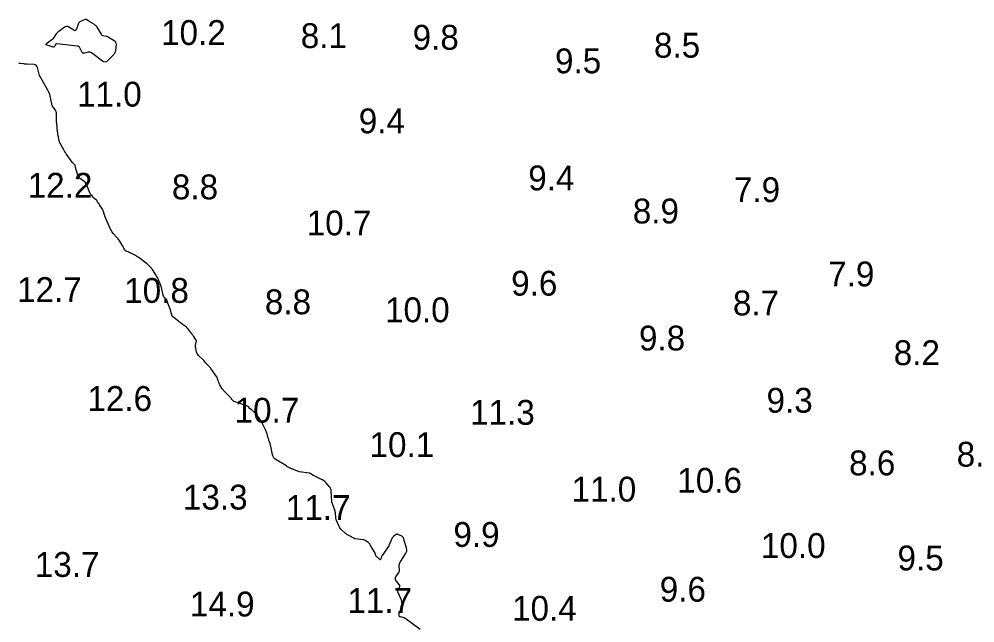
# Model space of a CAD drawing. Extents: x 815352 to 820877, y 582403 to 597439.
# Drawn here: x 819249.1 to 819441.4, y 594050.8 to 594172.3 of the extents above; entities that cross this region are included whole.
import ezdxf

# ---------------------------------------------------------------- set-up
doc = ezdxf.new("R2010")
doc.units = 0
doc.layers.add('V-CONT-EL12', color=7, linetype='Continuous')
doc.layers.add('V-TOPO-SOUN', color=7, linetype='Continuous')

msp = doc.modelspace()

# ---------------------------------------------------------------- linework, layer by layer
at = {"layer": 'V-CONT-EL12'}
msp.add_lwpolyline([(819256.61, 594167.35), (819256.52, 594167.32), (819256.45, 594167.27), (819256.4, 594167.18), (819256.22, 594166.79), (819256.16, 594166.71), (819256.1, 594166.66), (819256.01, 594166.65), (819255.92, 594166.66), (819254.73, 594167.04), (819254.55, 594167.12), (819254.47, 594167.22), (819254.51, 594167.34), (819254.65, 594167.48), (819255.91, 594168.42), (819255.92, 594168.43), (819255.93, 594168.43), (819255.94, 594168.43), (819255.95, 594168.43), (819255.99, 594168.41), (819256, 594168.41), (819256.01, 594168.41), (819256.01, 594168.41), (819256.02, 594168.42), (819256.61, 594169.33), (819256.71, 594169.48), (819256.83, 594169.62), (819256.96, 594169.75), (819257.1, 594169.88), (819258.15, 594170.72), (819258.37, 594170.85), (819258.6, 594170.91), (819258.84, 594170.88), (819259.08, 594170.77), (819260.11, 594170.13), (819260.3, 594170.04), (819260.46, 594170.05), (819260.59, 594170.14), (819260.69, 594170.34), (819261.03, 594171.39), (819261.1, 594171.56), (819261.21, 594171.7), (819261.35, 594171.82), (819261.52, 594171.91), (819262.46, 594172.29), (819262.54, 594172.31), (819262.61, 594172.31), (819262.67, 594172.29), (819262.74, 594172.24), (819262.99, 594172.03), (819263.05, 594171.98), (819263.12, 594171.93), (819263.19, 594171.88), (819263.26, 594171.84), (819264.18, 594171.28), (819264.35, 594171.16), (819264.5, 594171.02), (819264.63, 594170.87), (819264.75, 594170.7), (819265.57, 594169.28), (819265.65, 594169.16), (819265.75, 594169.08), (819265.87, 594169.02), (819266, 594168.98), (819266.57, 594168.9), (819266.71, 594168.87), (819266.85, 594168.83), (819266.98, 594168.77), (819267.1, 594168.7), (819268.19, 594168.01), (819268.38, 594167.85), (819268.51, 594167.66), (819268.57, 594167.45), (819268.58, 594167.2), (819268.47, 594166.02), (819268.42, 594165.74), (819268.33, 594165.49), (819268.19, 594165.25), (819268.01, 594165.04), (819266.9, 594163.91), (819266.65, 594163.71), (819266.38, 594163.64), (819266.11, 594163.68), (819265.83, 594163.84), (819263.65, 594165.5), (819263.49, 594165.6), (819263.33, 594165.66), (819263.15, 594165.67), (819262.97, 594165.65), (819262.21, 594165.46), (819262.04, 594165.44), (819261.89, 594165.47), (819261.77, 594165.57), (819261.68, 594165.71), (819261.23, 594166.69), (819261.21, 594166.72), (819261.19, 594166.74), (819261.16, 594166.76), (819261.13, 594166.78), (819260.99, 594166.83), (819260.96, 594166.84), (819260.92, 594166.85), (819260.89, 594166.86), (819260.85, 594166.86), (819256.7, 594167.35)], close=True, dxfattribs=at)
msp.add_lwpolyline([(819329.79, 594049.45), (819326.67, 594051.71), (819326.57, 594051.78), (819326.47, 594051.83), (819326.36, 594051.87), (819326.25, 594051.9), (819325.78, 594051.99), (819325.68, 594052.02), (819325.61, 594052.08), (819325.56, 594052.16), (819325.54, 594052.27), (819325.51, 594052.97), (819325.51, 594053.01), (819325.52, 594053.04), (819325.55, 594053.06), (819325.59, 594053.08), (819325.75, 594053.11), (819325.79, 594053.13), (819325.82, 594053.15), (819325.84, 594053.18), (819325.85, 594053.21), (819326.09, 594054.47), (819326.12, 594054.7), (819326.11, 594054.91), (819326.07, 594055.13), (819325.99, 594055.34), (819325.33, 594056.91), (819325.28, 594057.05), (819325.27, 594057.18), (819325.29, 594057.32), (819325.35, 594057.45), (819325.63, 594057.98), (819325.67, 594058.11), (819325.68, 594058.24), (819325.65, 594058.36), (819325.58, 594058.48), (819324.89, 594059.34), (819324.78, 594059.51), (819324.75, 594059.69), (819324.77, 594059.88), (819324.87, 594060.06), (819325.49, 594060.93), (819325.56, 594061.05), (819325.6, 594061.18), (819325.62, 594061.31), (819325.61, 594061.45), (819325.53, 594062.09), (819325.52, 594062.19), (819325.53, 594062.29), (819325.54, 594062.39), (819325.57, 594062.49), (819325.69, 594062.87), (819325.72, 594062.97), (819325.76, 594063.06), (819325.81, 594063.15), (819325.86, 594063.23), (819326.83, 594064.67), (819326.98, 594064.94), (819327.06, 594065.22), (819327.07, 594065.52), (819327.02, 594065.82), (819326.5, 594067.65), (819326.47, 594067.74), (819326.43, 594067.82), (819326.38, 594067.89), (819326.32, 594067.96), (819326.05, 594068.22), (819325.99, 594068.28), (819325.91, 594068.33), (819325.83, 594068.38), (819325.75, 594068.41), (819325.28, 594068.6), (819325.18, 594068.63), (819325.08, 594068.63), (819324.98, 594068.6), (819324.89, 594068.55), (819324.41, 594068.19), (819324.31, 594068.1), (819324.22, 594068), (819324.15, 594067.89), (819324.08, 594067.77), (819323.64, 594066.75), (819323.54, 594066.54), (819323.43, 594066.33), (819323.32, 594066.13), (819323.19, 594065.93), (819322.12, 594064.35), (819322.07, 594064.27), (819322.02, 594064.18), (819321.98, 594064.09), (819321.95, 594063.99), (819321.83, 594063.61), (819321.79, 594063.53), (819321.75, 594063.5), (819321.69, 594063.51), (819321.62, 594063.56), (819320.88, 594064.32), (819320.85, 594064.35), (819320.83, 594064.39), (819320.81, 594064.43), (819320.8, 594064.47), (819320.78, 594064.65), (819320.77, 594064.69), (819320.75, 594064.73), (819320.74, 594064.78), (819320.72, 594064.81), (819319.72, 594066.5), (819319.64, 594066.62), (819319.54, 594066.74), (819319.44, 594066.84), (819319.32, 594066.94), (819318.84, 594067.3), (819318.72, 594067.38), (819318.59, 594067.44), (819318.45, 594067.49), (819318.31, 594067.52), (819316.7, 594067.73), (819316.62, 594067.75), (819316.54, 594067.77), (819316.47, 594067.8), (819316.39, 594067.84), (819316.11, 594068.01), (819316.03, 594068.05), (819315.96, 594068.09), (819315.89, 594068.13), (819315.82, 594068.17), (819315.17, 594068.51), (819315.04, 594068.58), (819314.92, 594068.66), (819314.8, 594068.75), (819314.69, 594068.85), (819313.96, 594069.53), (819313.81, 594069.68), (819313.68, 594069.85), (819313.57, 594070.03), (819313.47, 594070.22), (819312.94, 594071.43), (819312.88, 594071.59), (819312.83, 594071.75), (819312.8, 594071.92), (819312.78, 594072.09), (819312.74, 594072.78), (819312.72, 594072.96), (819312.69, 594073.12), (819312.65, 594073.29), (819312.6, 594073.46), (819312.13, 594074.75), (819312.11, 594074.79), (819312.1, 594074.83), (819312.08, 594074.87), (819312.07, 594074.91), (819312, 594075.07), (819311.99, 594075.11), (819311.98, 594075.15), (819311.97, 594075.19), (819311.97, 594075.23), (819311.87, 594077.33), (819311.83, 594077.59), (819311.76, 594077.84), (819311.64, 594078.06), (819311.48, 594078.27), (819310.76, 594079.06), (819310.57, 594079.25), (819310.36, 594079.41), (819310.14, 594079.56), (819309.91, 594079.68), (819308.42, 594080.39), (819308.34, 594080.43), (819308.25, 594080.47), (819308.17, 594080.52), (819308.1, 594080.58), (819307.79, 594080.79), (819307.71, 594080.84), (819307.63, 594080.88), (819307.54, 594080.91), (819307.45, 594080.93), (819305.5, 594081.22), (819305.36, 594081.24), (819305.22, 594081.28), (819305.08, 594081.32), (819304.95, 594081.37), (819304.41, 594081.59), (819304.28, 594081.65), (819304.15, 594081.7), (819304.02, 594081.77), (819303.89, 594081.83), (819303.36, 594082.09), (819303.23, 594082.16), (819303.1, 594082.22), (819302.97, 594082.3), (819302.85, 594082.37), (819300.81, 594083.59), (819300.54, 594083.78), (819300.33, 594084.02), (819300.18, 594084.3), (819300.08, 594084.61), (819299.71, 594086.36), (819299.68, 594086.5), (819299.65, 594086.64), (819299.61, 594086.77), (819299.56, 594086.91), (819299.39, 594087.44), (819299.34, 594087.58), (819299.3, 594087.71), (819299.26, 594087.84), (819299.22, 594087.98), (819298.98, 594088.82), (819298.93, 594088.99), (819298.87, 594089.17), (819298.79, 594089.34), (819298.71, 594089.51), (819298.31, 594090.32), (819298.26, 594090.42), (819298.21, 594090.51), (819298.17, 594090.61), (819298.12, 594090.7), (819297.95, 594091.09), (819297.9, 594091.19), (819297.85, 594091.28), (819297.8, 594091.37), (819297.74, 594091.46), (819297.3, 594092.13), (819297.2, 594092.27), (819297.1, 594092.4), (819296.99, 594092.53), (819296.88, 594092.66), (819296.19, 594093.4), (819296.12, 594093.47), (819296.04, 594093.55), (819295.95, 594093.61), (819295.86, 594093.67), (819295.36, 594094), (819295.34, 594094.02), (819295.33, 594094.04), (819295.33, 594094.06), (819295.33, 594094.08), (819295.35, 594094.18), (819295.35, 594094.2), (819295.34, 594094.22), (819295.33, 594094.24), (819295.31, 594094.25), (819295.05, 594094.38), (819295, 594094.41), (819294.94, 594094.43), (819294.89, 594094.45), (819294.84, 594094.47), (819292.37, 594095.33), (819292.28, 594095.37), (819292.21, 594095.42), (819292.14, 594095.48), (819292.07, 594095.54), (819291.84, 594095.84), (819291.78, 594095.92), (819291.72, 594095.99), (819291.66, 594096.06), (819291.59, 594096.13), (819290.42, 594097.33), (819290.29, 594097.47), (819290.17, 594097.62), (819290.06, 594097.77), (819289.95, 594097.93), (819289.48, 594098.71), (819289.43, 594098.81), (819289.38, 594098.91), (819289.33, 594099.02), (819289.29, 594099.13), (819289.1, 594099.66), (819289.08, 594099.72), (819289.05, 594099.78), (819289.03, 594099.84), (819289.01, 594099.91), (819288.92, 594100.15), (819288.89, 594100.22), (819288.86, 594100.27), (819288.83, 594100.33), (819288.79, 594100.39), (819287.66, 594102.02), (819287.57, 594102.14), (819287.47, 594102.26), (819287.37, 594102.37), (819287.26, 594102.48), (819286.73, 594103), (819286.67, 594103.06), (819286.61, 594103.12), (819286.56, 594103.19), (819286.5, 594103.26), (819286.3, 594103.53), (819286.25, 594103.6), (819286.19, 594103.66), (819286.14, 594103.72), (819286.07, 594103.78), (819285.16, 594104.63), (819285.01, 594104.79), (819284.9, 594104.96), (819284.82, 594105.15), (819284.77, 594105.36), (819284.59, 594106.42), (819284.58, 594106.54), (819284.58, 594106.66), (819284.59, 594106.78), (819284.61, 594106.89), (819284.73, 594107.36), (819284.74, 594107.47), (819284.74, 594107.58), (819284.71, 594107.69), (819284.65, 594107.79), (819284.22, 594108.44), (819284.13, 594108.58), (819284.03, 594108.72), (819283.93, 594108.85), (819283.83, 594108.99), (819283.01, 594110.02), (819282.93, 594110.12), (819282.84, 594110.2), (819282.76, 594110.29), (819282.66, 594110.36), (819282.27, 594110.66), (819282.18, 594110.73), (819282.08, 594110.8), (819281.99, 594110.87), (819281.89, 594110.94), (819281.5, 594111.22), (819281.41, 594111.3), (819281.31, 594111.37), (819281.22, 594111.44), (819281.12, 594111.52), (819279.99, 594112.42), (819279.91, 594112.49), (819279.85, 594112.57), (819279.81, 594112.66), (819279.78, 594112.76), (819279.69, 594113.18), (819279.67, 594113.29), (819279.64, 594113.39), (819279.61, 594113.5), (819279.58, 594113.6), (819278.81, 594115.65), (819278.78, 594115.73), (819278.74, 594115.8), (819278.69, 594115.87), (819278.64, 594115.93), (819278.4, 594116.16), (819278.35, 594116.23), (819278.3, 594116.29), (819278.26, 594116.36), (819278.22, 594116.44), (819278.09, 594116.75), (819278.06, 594116.83), (819278.03, 594116.91), (819278.01, 594116.99), (819277.99, 594117.07), (819277.71, 594118.32), (819277.67, 594118.5), (819277.61, 594118.67), (819277.56, 594118.84), (819277.49, 594119.01), (819277.14, 594119.84), (819277.1, 594119.92), (819277.06, 594120.01), (819277.02, 594120.09), (819276.97, 594120.18), (819276.78, 594120.51), (819276.73, 594120.59), (819276.68, 594120.67), (819276.63, 594120.75), (819276.58, 594120.84), (819275.92, 594121.92), (819275.87, 594122), (819275.81, 594122.07), (819275.75, 594122.14), (819275.69, 594122.21), (819275.42, 594122.46), (819275.36, 594122.52), (819275.29, 594122.58), (819275.23, 594122.65), (819275.17, 594122.71), (819274.92, 594122.97), (819274.86, 594123.03), (819274.79, 594123.09), (819274.72, 594123.15), (819274.65, 594123.2), (819273.23, 594124.25), (819273.05, 594124.38), (819272.87, 594124.49), (819272.69, 594124.6), (819272.5, 594124.71), (819271.58, 594125.19), (819271.47, 594125.25), (819271.36, 594125.3), (819271.25, 594125.35), (819271.14, 594125.39), (819270.67, 594125.58), (819270.57, 594125.63), (819270.49, 594125.69), (819270.42, 594125.77), (819270.37, 594125.85), (819270.16, 594126.23), (819270.11, 594126.33), (819270.06, 594126.42), (819270, 594126.51), (819269.95, 594126.6), (819269.36, 594127.59), (819269.23, 594127.79), (819269.1, 594127.97), (819268.96, 594128.15), (819268.82, 594128.32), (819268.04, 594129.17), (819267.87, 594129.38), (819267.72, 594129.59), (819267.58, 594129.82), (819267.47, 594130.06), (819266.35, 594132.66), (819266.31, 594132.77), (819266.26, 594132.89), (819266.23, 594133), (819266.19, 594133.12), (819266.07, 594133.59), (819266.03, 594133.71), (819265.99, 594133.82), (819265.93, 594133.93), (819265.87, 594134.03), (819265.29, 594134.94), (819265.24, 594135.02), (819265.19, 594135.1), (819265.14, 594135.17), (819265.09, 594135.25), (819264.87, 594135.56), (819264.82, 594135.64), (819264.76, 594135.71), (819264.7, 594135.77), (819264.64, 594135.84), (819264.4, 594136.1), (819264.34, 594136.17), (819264.28, 594136.23), (819264.21, 594136.3), (819264.15, 594136.36), (819263.64, 594136.87), (819263.54, 594136.98), (819263.45, 594137.1), (819263.38, 594137.23), (819263.32, 594137.36), (819262.73, 594138.91), (819262.63, 594139.12), (819262.51, 594139.31), (819262.36, 594139.48), (819262.18, 594139.63), (819261.43, 594140.18), (819261.26, 594140.33), (819261.11, 594140.5), (819261, 594140.69), (819260.91, 594140.9), (819260.51, 594142.16), (819260.49, 594142.24), (819260.47, 594142.32), (819260.45, 594142.4), (819260.43, 594142.48), (819260.36, 594142.81), (819260.34, 594142.89), (819260.31, 594142.96), (819260.26, 594143.03), (819260.21, 594143.08), (819259.95, 594143.3), (819259.89, 594143.35), (819259.83, 594143.41), (819259.78, 594143.48), (819259.73, 594143.54), (819258.74, 594144.95), (819258.57, 594145.2), (819258.4, 594145.46), (819258.24, 594145.73), (819258.09, 594145.99), (819257.3, 594147.4), (819257.24, 594147.51), (819257.2, 594147.62), (819257.16, 594147.73), (819257.14, 594147.85), (819257.05, 594148.34), (819257.03, 594148.45), (819257.01, 594148.55), (819256.99, 594148.66), (819256.97, 594148.77), (819256.89, 594149.2), (819256.87, 594149.31), (819256.85, 594149.42), (819256.84, 594149.53), (819256.82, 594149.64), (819256.66, 594151.35), (819256.64, 594151.58), (819256.63, 594151.81), (819256.62, 594152.04), (819256.62, 594152.27), (819256.61, 594153.26), (819256.59, 594153.45), (819256.55, 594153.62), (819256.48, 594153.79), (819256.38, 594153.95), (819255.94, 594154.57), (819255.84, 594154.73), (819255.75, 594154.9), (819255.69, 594155.07), (819255.64, 594155.25), (819255.31, 594156.81), (819255.24, 594157.13), (819255.13, 594157.44), (819255, 594157.74), (819254.85, 594158.03), (819253.45, 594160.49), (819253.32, 594160.74), (819253.21, 594160.99), (819253.11, 594161.25), (819253.04, 594161.51), (819252.77, 594162.59), (819252.68, 594162.83), (819252.54, 594163.01), (819252.34, 594163.12), (819252.09, 594163.16), (819250.73, 594163.23), (819250.56, 594163.24), (819250.39, 594163.25), (819250.22, 594163.27), (819250.05, 594163.28), (819249.37, 594163.36), (819249.21, 594163.39), (819249.06, 594163.45)], dxfattribs=at)

# ---------------------------------------------------------------- texts
at = {"layer": 'V-TOPO-SOUN'}
for s, p in [('10.2 ', (819277.64, 594167.1)), ('8.1', (819305.75, 594166.48)), ('9.8', (819328.25, 594166.15)), ('8.5', (819376.8, 594164.55)), ('9.5', (819356.89, 594161.4)), ('11.0 ', (819260.74, 594154.7)), ('9.4', (819317.42, 594149.32)), ('9.4', (819351.51, 594137.84)), ('12.2 ', (819250.81, 594136.36)), ('8.8', (819279.82, 594136.04)), ('7.9', (819392.88, 594135.48)), ('8.9', (819372.54, 594131.18)), ('10.7 ', (819306.94, 594128.78)), ('7.9', (819411.84, 594118.52)), ('12.7 ', (819248.67, 594115.37)), ('9.6', (819348.07, 594116.65)), ('10.8 ', (819270.23, 594115.2)), ('8.8', (819298.52, 594112.91)), ('8.7', (819392.68, 594112.68)), ('10.0 ', (819322.69, 594111.3)), ('9.8', (819373.78, 594105.62)), ('8.2', (819425.03, 594102.67)), ('12.6 ', (819262.82, 594093.45)), ('9.3', (819399.44, 594093.09)), ('10.7 ', (819292.44, 594091.09)), ('11.3 ', (819339.81, 594090.66)), ('10.1 ', (819319.58, 594084.17)), ('8.4', (819437.69, 594082.23)), ('8.6', (819416.05, 594080.49)), ('10.6 ', (819381.49, 594076.98)), ('11.0 ', (819360.22, 594075.21)), ('13.3 ', (819282.04, 594073.6)), ('11.7 ', (819302.74, 594071.5)), ('9.9', (819336.45, 594066.09)), ('10.0 ', (819398.31, 594063.86)), ('13.7 ', (819252.25, 594060.05)), ('9.5', (819425.79, 594061.36)), ('9.6', (819377.96, 594055.06)), ('14.9 ', (819283.45, 594052.08)), ('11.7 ', (819315.14, 594052.8)), ('10.4 ', (819348.25, 594051.23))]:
    msp.add_text(s, height=5, dxfattribs=at).set_placement(p)

doc.saveas('drawing.dxf')
